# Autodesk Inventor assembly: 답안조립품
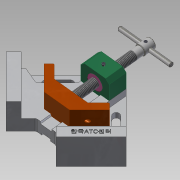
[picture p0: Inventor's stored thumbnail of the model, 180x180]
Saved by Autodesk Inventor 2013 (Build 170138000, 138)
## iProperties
Created: 2019-04
Part Number: 답안조립품
Document SubType Name: Assembly
Designer: Administrator
Author: Administrator
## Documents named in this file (11)
- C:\Users\Administrator\Desktop\490407v1011\답안조립품.iam
- C:\Users\Administrator\Desktop\490407v1011\베이스.ipt
- C:\Users\Administrator\Desktop\490407v1011\리드스크류.ipt
- C:\Users\Administrator\Desktop\490407v1011\멈춤나사 M4x5.ipt
- C:\Users\Administrator\Desktop\490407v1011\멈춤나사 M4x10.ipt
- C:\Users\Administrator\Desktop\490407v1011\볼트 M4x16.ipt
- C:\Users\Administrator\Desktop\490407v1011\부시.ipt
- C:\Users\Administrator\Desktop\490407v1011\서포트.ipt
- C:\Users\Administrator\Desktop\490407v1011\조.ipt
- C:\Users\Administrator\Desktop\490407v1011\평행 핀 2.5x24.ipt
- C:\Users\Administrator\Desktop\490407v1011\핸들.ipt
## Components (1 placed, 1 different names)
1. 핸들:1
